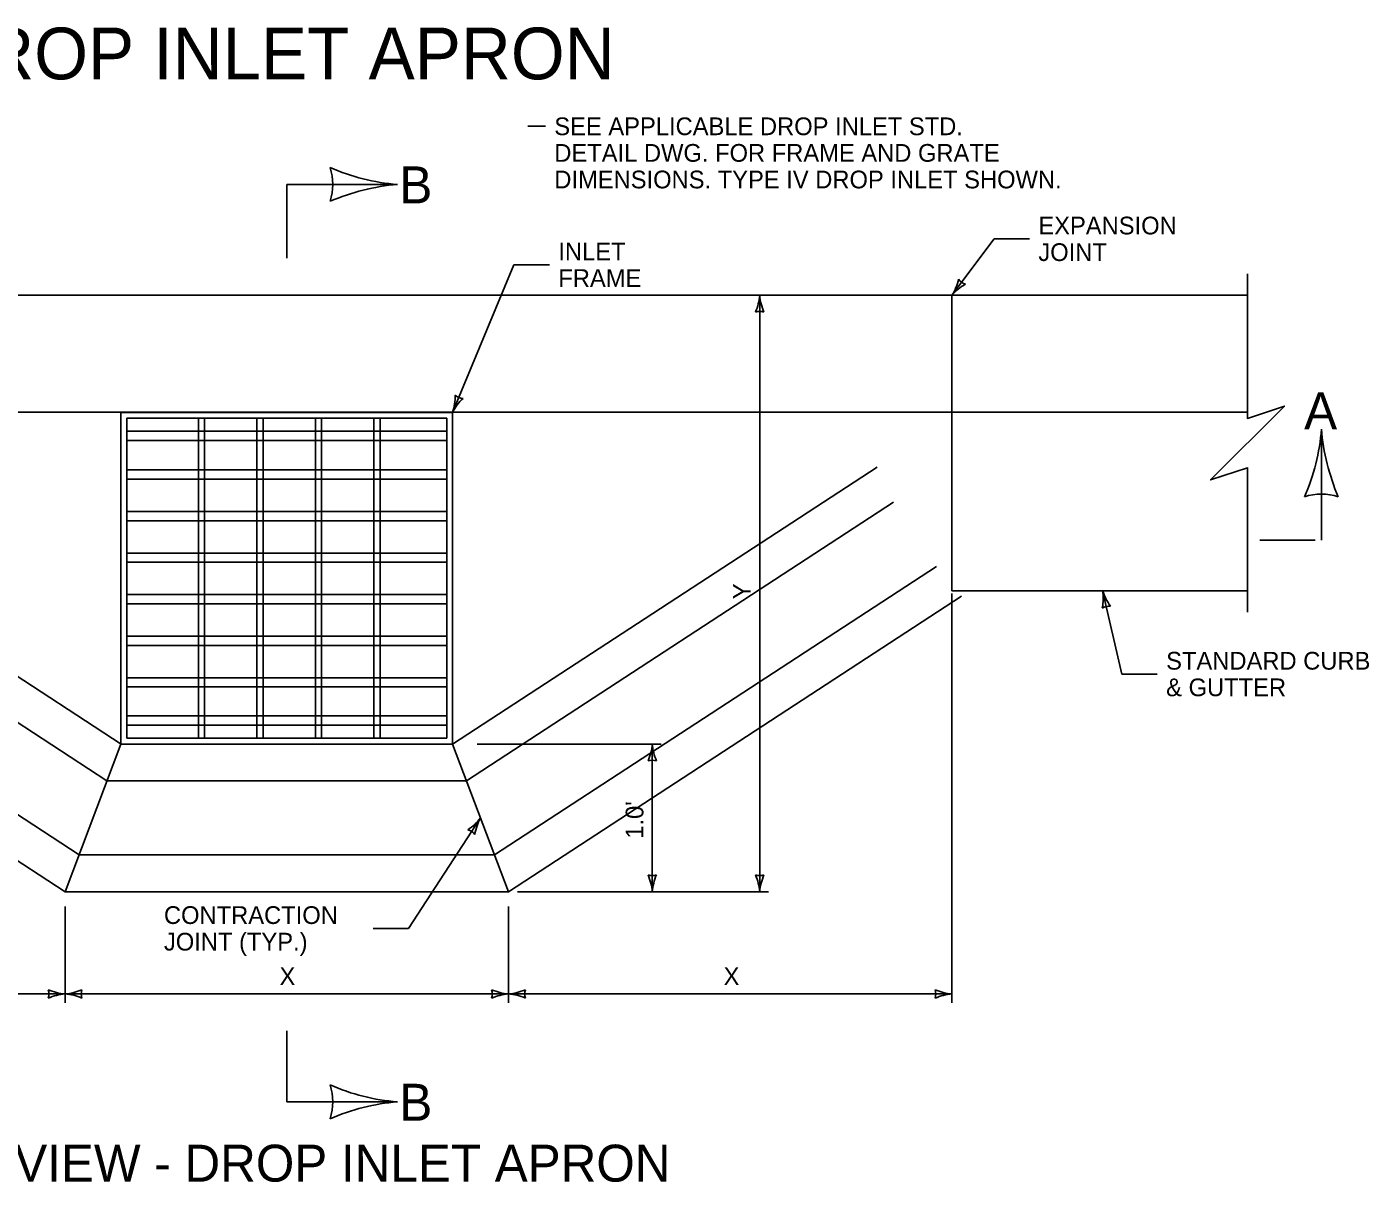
# Model space of a CAD drawing. Extents: x 49991.4 to 50048.3, y 49987.6 to 50018.3.
# Drawn here: x 50039.25 to 50048.33, y 50010.48 to 50018.29 of the extents above; entities that cross this region are included whole.
import ezdxf

# ---------------------------------------------------------------- set-up
doc = ezdxf.new("R2010")
doc.units = 0
doc.layers.add('Level 1', color=7, linetype='Continuous')

# ---------------------------------------------------------------- blocks, each defined once
blk = doc.blocks.new('Arr1')
at = {"layer": 'Level 1'}
for centre, radius, start, end in [((0.0003380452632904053, 0.004588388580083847), 0.0046008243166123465, 246.13281152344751, 265.7863990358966), ((-0.002683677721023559, 2.2053718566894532e-10), 0.0012211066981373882, 341.8194575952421, 18.18051657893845), ((0.00040889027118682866, -0.004871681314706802), 0.004888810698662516, 94.79770847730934, 113.28308350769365)]:
    blk.add_arc(centre, radius, start, end, dxfattribs=at)

msp = doc.modelspace()

# ---------------------------------------------------------------- linework, layer by layer
at = {"layer": 'Level 1'}
for p, q in [((50042.7607293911, 50017.62085235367), (50042.6407293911, 50017.62085235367)), ((50041.010700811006, 50017.22753518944), (50041.760700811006, 50017.22753518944)), ((50041.010700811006, 50016.72753518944), (50041.010700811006, 50017.22753518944)), ((50045.510700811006, 50016.47753518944), (50045.79573416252, 50016.85917797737)), ((50046.03573416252, 50016.85917797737), (50045.79573416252, 50016.85917797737)), ((50042.13274805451, 50015.68470385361), (50042.54788659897, 50016.6836864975)), ((50042.78788659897, 50016.6836864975), (50042.54788659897, 50016.6836864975)), ((50036.51070081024, 50016.47753518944), (50045.510700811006, 50016.47753518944)), ((50044.210465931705, 50012.44020185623), (50044.210465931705, 50016.47753518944)), ((50045.510700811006, 50014.47753518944), (50045.510700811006, 50016.47753518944)), ((50045.510700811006, 50016.47753518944), (50047.510700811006, 50016.47753518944)), ((50034.51070081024, 50015.68586852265), (50047.510700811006, 50015.68586852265)), ((50039.88865356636, 50015.684703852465), (50042.13274805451, 50015.684703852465)), ((50039.88865356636, 50013.44060936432), (50039.88865356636, 50015.68470385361)), ((50042.09337797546, 50015.645333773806), (50039.92802364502, 50015.645333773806)), ((50039.928023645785, 50013.479979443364), (50039.92802364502, 50015.645333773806)), ((50040.412388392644, 50013.479979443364), (50040.412388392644, 50015.645333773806)), ((50040.454055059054, 50013.479979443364), (50040.454055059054, 50015.645333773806)), ((50040.80822172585, 50013.479979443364), (50040.80822172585, 50015.645333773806)), ((50040.84988839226, 50013.479979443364), (50040.84988839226, 50015.645333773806)), ((50041.204055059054, 50013.479979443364), (50041.204055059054, 50015.645333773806)), ((50041.24572172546, 50013.479979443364), (50041.24572172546, 50015.645333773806)), ((50041.59988839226, 50013.479979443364), (50041.59988839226, 50015.645333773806)), ((50041.641555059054, 50013.479979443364), (50041.641555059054, 50015.645333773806)), ((50042.09337797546, 50013.479979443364), (50042.09337797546, 50015.645333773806)), ((50042.13274805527, 50013.44060936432), (50042.13274805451, 50015.68470385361)), ((50042.09337797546, 50015.55675109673), (50039.92802364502, 50015.55675109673)), ((50048.010700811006, 50014.820673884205), (50048.010700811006, 50015.570673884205)), ((50042.09337797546, 50015.49441513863), (50039.92802364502, 50015.49441513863)), ((50039.88927783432, 50013.44020185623), (50037.04538776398, 50015.29663009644)), ((50042.09337797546, 50015.29516681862), (50039.92802364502, 50015.29516681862)), ((50042.13274805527, 50013.44060936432), (50045.00402376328, 50015.31491434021)), ((50042.09337797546, 50015.2326668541), (50039.92802364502, 50015.2326668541)), ((50039.79420386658, 50013.19060936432), (50036.99594192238, 50015.01725257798)), ((50042.09337797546, 50015.01391682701), (50039.92802364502, 50015.01391682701)), ((50042.227197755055, 50013.19060936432), (50045.11664080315, 50015.07677357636)), ((50042.09337797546, 50014.951416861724), (50039.92802364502, 50014.951416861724)), ((50047.96903414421, 50014.820673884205), (50047.59403414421, 50014.820673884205)), ((50042.09337797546, 50014.732666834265), (50039.92802364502, 50014.732666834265)), ((50039.60515051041, 50012.69020185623), (50036.61516706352, 50014.64199660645)), ((50042.09337797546, 50014.67016686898), (50039.92802364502, 50014.67016686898)), ((50042.416251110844, 50012.69020185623), (50045.40623455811, 50014.64199660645)), ((50045.510700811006, 50014.47753518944), (50047.51070081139, 50014.47753518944)), ((50045.510700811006, 50014.45920185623), (50045.510700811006, 50011.68914241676)), ((50046.53057611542, 50014.478604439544), (50046.66034155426, 50013.91399642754)), ((50039.51070081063, 50012.44020185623), (50036.51070081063, 50014.39853518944)), ((50042.09337797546, 50014.45141363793), (50039.92802364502, 50014.45141363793)), ((50042.09337797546, 50014.38891367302), (50039.92802364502, 50014.38891367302)), ((50042.510700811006, 50012.44020185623), (50045.57487140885, 50014.44042432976)), ((50042.09337797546, 50014.170163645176), (50039.92802364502, 50014.170163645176)), ((50042.09337797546, 50014.10766368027), (50039.92802364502, 50014.10766368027)), ((50046.90034155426, 50013.91399642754), (50046.66034155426, 50013.91399642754)), ((50042.09337797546, 50013.88891365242), (50039.92802364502, 50013.88891365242)), ((50042.09337797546, 50013.8264136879), (50039.92802364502, 50013.8264136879)), ((50042.09337797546, 50013.63089807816), (50039.92802364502, 50013.63089807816)), ((50042.09337797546, 50013.56856212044), (50039.92802364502, 50013.56856212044)), ((50042.09337797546, 50013.479979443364), (50039.92802364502, 50013.479979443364)), ((50039.88865356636, 50013.44060936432), (50039.51070081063, 50012.44020185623)), ((50042.13274805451, 50013.44060936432), (50039.88865356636, 50013.44060936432)), ((50039.88927783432, 50013.44020185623), (50042.13212378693, 50013.44020185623)), ((50042.13274805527, 50013.44060936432), (50042.510700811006, 50012.44020185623)), ((50042.2994147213, 50013.44020185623), (50043.54363799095, 50013.44020185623)), ((50043.483637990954, 50012.44020185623), (50043.483637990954, 50013.44020185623)), ((50039.79420386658, 50013.19060936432), (50042.227197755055, 50013.19060936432)), ((50042.32172443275, 50012.94040561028), (50041.834123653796, 50012.192755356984)), ((50039.60515051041, 50012.69020185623), (50042.416251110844, 50012.69020185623)), ((50039.51070081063, 50012.44020185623), (50042.510700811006, 50012.44020185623)), ((50042.570700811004, 50012.44020185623), (50044.2704659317, 50012.44020185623)), ((50039.51070081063, 50012.340201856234), (50039.51070081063, 50011.68914241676)), ((50042.510700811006, 50012.340201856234), (50042.510700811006, 50011.68914241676)), ((50041.5941236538, 50012.192755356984), (50041.834123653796, 50012.192755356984)), ((50036.51070081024, 50011.74914241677), (50039.51070081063, 50011.74914241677)), ((50039.51070081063, 50011.74914241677), (50042.510700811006, 50011.74914241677)), ((50042.510700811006, 50011.74914241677), (50045.510700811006, 50011.74914241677)), ((50041.010700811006, 50011.01920185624), (50041.010700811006, 50011.49914241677)), ((50041.010700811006, 50011.01920185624), (50041.760700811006, 50011.01920185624))]:
    msp.add_line(p, q, dxfattribs=at)
msp.add_lwpolyline([(50047.510700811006, 50014.33170185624), (50047.510700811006, 50015.30964591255), (50047.51110801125, 50015.30964591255), (50047.260700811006, 50015.22753518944), (50047.760700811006, 50015.72753518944), (50047.510700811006, 50015.64420185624), (50047.510700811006, 50016.62336852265)], dxfattribs=at)
for centre, radius, start, end in [((50045.19960853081, 50016.67160151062), 0.36666080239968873, 328.04316282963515, 346.5285378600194), ((50045.19960853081, 50016.67160151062), 0.36666080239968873, 328.04316282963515, 346.5285378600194), ((50045.77124809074, 50016.25129907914), 0.345061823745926, 119.37826587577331, 139.03185338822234), ((50045.77124809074, 50016.25129907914), 0.345061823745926, 119.37826587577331, 139.03185338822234), ((50045.63114189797, 50016.63879864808), 0.0915830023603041, 215.06491194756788, 251.4259709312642), ((50045.63114189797, 50016.63879864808), 0.0915830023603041, 215.06491194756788, 251.4259709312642), ((50043.86633678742, 50016.502888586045), 0.345061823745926, 336.1328115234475, 355.7863990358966), ((50043.86633678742, 50016.502888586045), 0.345061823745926, 336.1328115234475, 355.7863990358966), ((50044.575842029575, 50016.50820196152), 0.36666080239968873, 184.79770847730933, 203.28308350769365), ((50044.575842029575, 50016.50820196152), 0.36666080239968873, 184.79770847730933, 203.28308350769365), ((50044.21046591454, 50016.276259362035), 0.09158300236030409, 71.81945759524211, 108.18051657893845), ((50044.21046591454, 50016.276259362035), 0.09158300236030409, 71.81945759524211, 108.18051657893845), ((50041.78357731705, 50015.79659639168), 0.36666080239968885, 342.23182787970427, 0.7172029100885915), ((50041.78357731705, 50015.79659639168), 0.36666080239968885, 342.23182787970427, 0.7172029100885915), ((50042.44080104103, 50015.52923353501), 0.34506182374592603, 133.56693092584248, 153.22051843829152), ((50042.44080104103, 50015.52923353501), 0.34506182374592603, 133.56693092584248, 153.22051843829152), ((50042.20998676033, 50015.87056977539), 0.0915830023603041, 229.25357699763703, 265.6146359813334), ((50042.20998676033, 50015.87056977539), 0.0915830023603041, 229.25357699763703, 265.6146359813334), ((50046.189512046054, 50014.42623113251), 0.34506182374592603, 349.0764770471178, 8.73006455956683), ((50046.189512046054, 50014.42623113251), 0.34506182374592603, 349.0764770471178, 8.73006455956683), ((50046.87979914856, 50014.59033365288), 0.3666608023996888, 197.7413740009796, 216.2267490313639), ((50046.87979914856, 50014.59033365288), 0.3666608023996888, 197.7413740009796, 216.2267490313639), ((50046.57566045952, 50014.28244287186), 0.09158300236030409, 84.76312311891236, 121.1241821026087), ((50046.57566045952, 50014.28244287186), 0.09158300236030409, 84.76312311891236, 121.1241821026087), ((50043.13950884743, 50013.46555525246), 0.345061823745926, 336.1328115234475, 355.7863990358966), ((50043.13950884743, 50013.46555525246), 0.345061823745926, 336.1328115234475, 355.7863990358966), ((50043.84901408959, 50013.470868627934), 0.36666080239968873, 184.79770847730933, 203.28308350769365), ((50043.84901408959, 50013.470868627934), 0.36666080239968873, 184.79770847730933, 203.28308350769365), ((50043.483637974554, 50013.23892602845), 0.09158300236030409, 71.81945759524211, 108.18051657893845), ((50043.483637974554, 50013.23892602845), 0.09158300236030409, 71.81945759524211, 108.18051657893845), ((50042.04732850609, 50013.149629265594), 0.345061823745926, 303.0213196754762, 322.67490718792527), ((50042.04732850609, 50013.149629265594), 0.345061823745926, 303.0213196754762, 322.67490718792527), ((50042.6445191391, 50012.76649838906), 0.36666080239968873, 151.68621662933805, 170.17159165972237), ((50042.6445191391, 50012.76649838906), 0.36666080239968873, 151.68621662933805, 170.17159165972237), ((50042.21177347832, 50012.7718151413), 0.09158300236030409, 38.70796574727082, 75.06902473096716), ((50042.21177347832, 50012.7718151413), 0.09158300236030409, 38.70796574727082, 75.06902473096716), ((50043.11826189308, 50012.409535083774), 0.36666080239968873, 4.797708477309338, 23.28308350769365), ((50043.48363800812, 50012.64147768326), 0.0915830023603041, 251.8194575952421, 288.18051657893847), ((50043.48363800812, 50012.64147768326), 0.0915830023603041, 251.8194575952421, 288.18051657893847), ((50043.11826189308, 50012.409535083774), 0.36666080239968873, 4.797708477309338, 23.28308350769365), ((50043.82776713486, 50012.41484845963), 0.345061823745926, 156.13281152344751, 175.78639903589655), ((50043.82776713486, 50012.41484845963), 0.345061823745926, 156.13281152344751, 175.78639903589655), ((50043.845089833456, 50012.409535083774), 0.36666080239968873, 4.797708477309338, 23.28308350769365), ((50044.21046594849, 50012.64147768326), 0.0915830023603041, 251.8194575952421, 288.18051657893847), ((50044.21046594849, 50012.64147768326), 0.0915830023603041, 251.8194575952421, 288.18051657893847), ((50043.845089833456, 50012.409535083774), 0.36666080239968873, 4.797708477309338, 23.28308350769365), ((50044.55459507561, 50012.41484845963), 0.345061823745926, 156.13281152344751, 175.78639903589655), ((50044.55459507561, 50012.41484845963), 0.345061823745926, 156.13281152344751, 175.78639903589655), ((50039.30942498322, 50011.74914243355), 0.0915830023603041, 341.8194575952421, 18.180516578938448), ((50039.30942498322, 50011.74914243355), 0.0915830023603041, 341.8194575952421, 18.180516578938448), ((50039.54136758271, 50011.38376631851), 0.36666080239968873, 94.79770847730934, 113.28308350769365), ((50039.54136758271, 50011.38376631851), 0.36666080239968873, 94.79770847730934, 113.28308350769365), ((50039.53605420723, 50012.09327156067), 0.345061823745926, 246.13281152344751, 265.7863990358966), ((50039.53605420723, 50012.09327156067), 0.345061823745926, 246.13281152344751, 265.7863990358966), ((50039.48003403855, 50012.11451851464), 0.36666080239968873, 274.79770847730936, 293.2830835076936), ((50039.48003403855, 50012.11451851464), 0.36666080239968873, 274.79770847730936, 293.2830835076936), ((50039.48534741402, 50011.40501327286), 0.345061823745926, 66.13281152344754, 85.7863990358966), ((50039.48534741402, 50011.40501327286), 0.345061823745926, 66.13281152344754, 85.7863990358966), ((50039.71197663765, 50011.749142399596), 0.0915830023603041, 161.81945759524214, 198.18051657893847), ((50039.71197663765, 50011.749142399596), 0.0915830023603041, 161.81945759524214, 198.18051657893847), ((50042.30942498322, 50011.74914243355), 0.0915830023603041, 341.8194575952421, 18.180516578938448), ((50042.30942498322, 50011.74914243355), 0.0915830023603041, 341.8194575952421, 18.180516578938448), ((50042.541367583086, 50011.38376631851), 0.36666080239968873, 94.79770847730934, 113.28308350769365), ((50042.541367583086, 50011.38376631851), 0.36666080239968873, 94.79770847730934, 113.28308350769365), ((50042.53605420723, 50012.09327156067), 0.345061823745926, 246.13281152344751, 265.7863990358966), ((50042.53605420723, 50012.09327156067), 0.345061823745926, 246.13281152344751, 265.7863990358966), ((50042.48003403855, 50012.11451851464), 0.36666080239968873, 274.79770847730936, 293.2830835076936), ((50042.48003403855, 50012.11451851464), 0.36666080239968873, 274.79770847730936, 293.2830835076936), ((50042.485347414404, 50011.40501327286), 0.345061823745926, 66.13281152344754, 85.7863990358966), ((50042.485347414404, 50011.40501327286), 0.345061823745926, 66.13281152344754, 85.7863990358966), ((50042.711976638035, 50011.749142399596), 0.0915830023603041, 161.81945759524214, 198.18051657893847), ((50042.711976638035, 50011.749142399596), 0.0915830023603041, 161.81945759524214, 198.18051657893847), ((50045.30942498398, 50011.74914243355), 0.0915830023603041, 341.8194575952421, 18.180516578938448), ((50045.30942498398, 50011.74914243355), 0.0915830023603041, 341.8194575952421, 18.180516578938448), ((50045.541367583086, 50011.38376631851), 0.36666080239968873, 94.79770847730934, 113.28308350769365), ((50045.541367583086, 50011.38376631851), 0.36666080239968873, 94.79770847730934, 113.28308350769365), ((50045.536054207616, 50012.09327156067), 0.345061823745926, 246.13281152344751, 265.7863990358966), ((50045.536054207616, 50012.09327156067), 0.345061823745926, 246.13281152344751, 265.7863990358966)]:
    msp.add_arc(centre, radius, start, end, dxfattribs=at)

# ---------------------------------------------------------------- block references
at = {"layer": 'Level 1', "xscale": 300, "yscale": 300}
for p in [(50041.760700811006, 50017.22753518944), (50041.760700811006, 50011.01920185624)]:
    msp.add_blockref('Arr1', p, dxfattribs=at)
at = {"layer": 'Level 1', "xscale": 300, "yscale": 300, "rotation": 90}
msp.add_blockref('Arr1', (50048.010700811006, 50015.570673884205), dxfattribs=at)
msp.add_blockref('Arr1', (50048.010700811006, 50015.570673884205), dxfattribs=at)

# ---------------------------------------------------------------- texts
at = {"layer": 'Level 1'}
for s, height, p in [('DROP INLET APRON', 0.35, (50038.62579227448, 50017.93874029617)), ('SEE APPLICABLE DROP INLET STD.', 0.12000000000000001, (50042.820729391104, 50017.56085235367)), ('DETAIL DWG. FOR FRAME AND GRATE', 0.12000000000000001, (50042.820729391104, 50017.38085235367)), ('B', 0.25, (50041.772705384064, 50017.09956827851)), ('DIMENSIONS. TYPE IV DROP INLET SHOWN.', 0.12000000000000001, (50042.820729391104, 50017.20085235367)), ('EXPANSION', 0.12000000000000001, (50046.095734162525, 50016.88917797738)), ('INLET', 0.12000000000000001, (50042.84788659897, 50016.7136864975)), ('JOINT', 0.12000000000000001, (50046.095734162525, 50016.70917797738)), ('FRAME', 0.12000000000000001, (50042.84788659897, 50016.5336864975)), ('A', 0.25, (50047.89389440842, 50015.570673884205)), ('STANDARD CURB', 0.12000000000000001, (50046.960341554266, 50013.94399642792)), ('& GUTTER', 0.12000000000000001, (50046.960341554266, 50013.76399642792)), ('CONTRACTION', 0.12000000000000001, (50040.17966770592, 50012.22275535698)), ('JOINT (TYP.)', 0.12000000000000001, (50040.17966770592, 50012.04275535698)), ('X', 0.11979166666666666, (50040.961651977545, 50011.80924658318)), ('X', 0.11979166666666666, (50043.966227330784, 50011.80924658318)), ('B', 0.25, (50041.772705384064, 50010.8912349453)), ('PLAN VIEW - DROP INLET APRON', 0.25, (50038.20096376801, 50010.4789537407))]:
    msp.add_text(s, height=height, dxfattribs=at).set_placement(p)
for s, p in [('Y', (50044.15036176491, 50014.42030050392)), ("1.0'", (50043.42353382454, 50012.79993168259))]:
    msp.add_text(s, height=0.11979166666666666, rotation=90, dxfattribs=at).set_placement(p)

doc.saveas('drawing.dxf')
